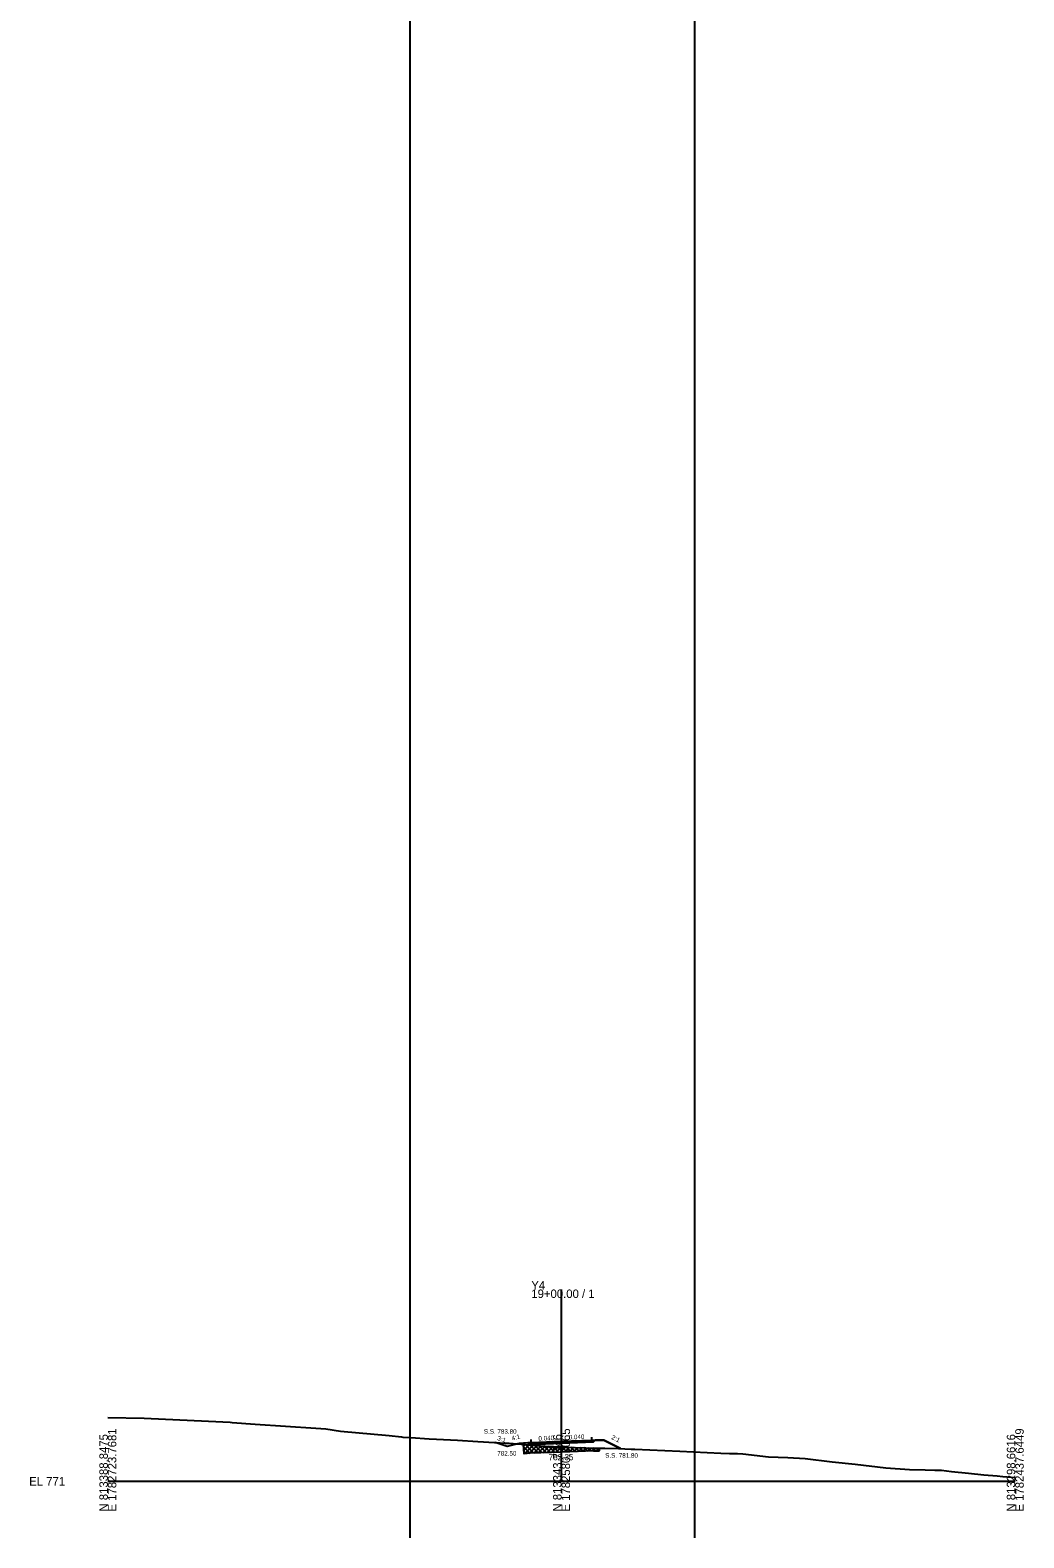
# Model space of a CAD drawing. Extents: x -26 to 3903, y -10 to 9562.
# Drawn here: x 974.3 to 1302.8, y 981.3 to 1479.6 of the extents above; entities that cross this region are included whole.
import ezdxf

# ---------------------------------------------------------------- set-up
doc = ezdxf.new("R2010")
doc.units = 0
for name, color, linetype in [('Exist Cross Section Cell', 7, 'Continuous'), ('Exist XS Center Line Elevation Label', 7, 'Continuous'), ('Exist XS Ground Line', 7, 'Continuous'), ('Prop XS Ditch Slope Text', 7, 'Continuous'), ('Prop XS Ditch Standard Text', 7, 'Continuous'), ('Prop XS Dump Level', 7, 'Continuous'), ('Prop XS Earthwork Shape', 7, 'Continuous'), ('Prop XS Earthwork Undercut', 7, 'Continuous'), ('Prop XS EOT Tick Mark', 7, 'Continuous'), ('Prop XS Finish Grade', 7, 'Continuous'), ('Prop XS Finish Grade Earthwork', 7, 'Continuous'), ('Prop XS Finish Grade Pavement', 7, 'Continuous'), ('Prop XS Pvmt Edge Slope', 7, 'Continuous'), ('Prop XS SE Text', 7, 'Continuous'), ('Prop XS Side Slope Text', 7, 'Continuous'), ('Prop XS SS Elevation Text', 7, 'Continuous'), ('Prop XS Subgrade Earthwork', 7, 'Continuous'), ('Prop XS Undercut Exc Hatch', 7, 'Continuous'), ('Scratch_Level_1', 7, 'Continuous'), ('Scratch_Level_2', 7, 'Continuous'), ('Scratch_Level_4', 7, 'Continuous'), ('Scratch_Level_6', 7, 'Continuous')]:
    doc.layers.add(name, color=color, linetype=linetype)

msp = doc.modelspace()

# ---------------------------------------------------------------- linework, layer by layer
at = {"layer": 'Exist Cross Section Cell'}
for p, q in [((1150, 1000), (1150, 1063.39)), ((1000, 1000), (1150, 1000)), ((1150, 1000), (1300, 1000))]:
    msp.add_line(p, q, dxfattribs=at)
at = {"layer": 'Exist XS Ground Line'}
for p, q in [((1000, 1021.13), (1011.96, 1020.92)), ((1011.96, 1020.92), (1037.96, 1019.6)), ((1037.96, 1019.6), (1040.4, 1019.5)), ((1040.4, 1019.5), (1041.07, 1019.45)), ((1041.07, 1019.45), (1048.74, 1018.93)), ((1048.74, 1018.93), (1068.81, 1017.56)), ((1068.81, 1017.56), (1072.02, 1017.39)), ((1072.02, 1017.39), (1076.91, 1016.62)), ((1076.91, 1016.62), (1092.96, 1015.09)), ((1092.96, 1015.09), (1097.12, 1014.66)), ((1097.12, 1014.66), (1097.51, 1014.61)), ((1097.51, 1014.61), (1100.13, 1014.46)), ((1100.13, 1014.46), (1106.24, 1014.08)), ((1106.24, 1014.08), (1108.69, 1013.95)), ((1108.69, 1013.95), (1115.61, 1013.56)), ((1115.61, 1013.56), (1122.3, 1013.15)), ((1122.3, 1013.15), (1127.87, 1012.81)), ((1127.87, 1012.81), (1131.34, 1012.64)), ((1131.34, 1012.64), (1132.64, 1012.58)), ((1132.64, 1012.58), (1138.01, 1012.14)), ((1138.01, 1012.14), (1141.64, 1011.84)), ((1141.64, 1011.84), (1144.56, 1011.64)), ((1144.56, 1011.64), (1150, 1011.35)), ((1150, 1011.35), (1150.63, 1011.32)), ((1150.63, 1011.32), (1158.01, 1011.11)), ((1158.01, 1011.11), (1162.5, 1010.97)), ((1162.5, 1010.97), (1164.35, 1010.99)), ((1164.35, 1010.99), (1168.84, 1010.83)), ((1168.84, 1010.83), (1172.96, 1010.67)), ((1172.96, 1010.67), (1174.18, 1010.59)), ((1174.18, 1010.59), (1189.07, 1009.95)), ((1189.07, 1009.95), (1202.68, 1009.27)), ((1202.68, 1009.27), (1205.5, 1009.22)), ((1205.5, 1009.22), (1208.16, 1009.19)), ((1208.16, 1009.19), (1209.9, 1009.08)), ((1209.9, 1009.08), (1218.39, 1008.08)), ((1218.39, 1008.08), (1224.8, 1007.88)), ((1224.8, 1007.88), (1230.59, 1007.57)), ((1230.59, 1007.57), (1239.46, 1006.47)), ((1239.46, 1006.47), (1247.1, 1005.69)), ((1247.1, 1005.69), (1257.22, 1004.44)), ((1257.22, 1004.44), (1265.08, 1003.89)), ((1265.08, 1003.89), (1270.24, 1003.74)), ((1270.24, 1003.74), (1273.4, 1003.68)), ((1273.4, 1003.68), (1275.59, 1003.64)), ((1275.59, 1003.64), (1278.88, 1003.26)), ((1278.88, 1003.26), (1284.53, 1002.69)), ((1284.53, 1002.69), (1289.66, 1002.18)), ((1289.66, 1002.18), (1294.02, 1001.8)), ((1294.02, 1001.8), (1295.89, 1001.55)), ((1295.89, 1001.55), (1300, 1001.22))]:
    msp.add_line(p, q, dxfattribs=at)
at = {"layer": 'Prop XS Dump Level'}
for p, q in [((1140, 1012.82), (1150, 1013.22)), ((1150, 1013.22), (1160, 1013.62))]:
    msp.add_line(p, q, dxfattribs=at)
at = {"layer": 'Prop XS Earthwork Shape'}
for points in [[(1135.41, 1012.35), (1132, 1011.5), (1128.09, 1012.8), (1131.34, 1012.64), (1132.64, 1012.58)], [(1138.87, 1012.73), (1136, 1012.5), (1135.41, 1012.35), (1138.01, 1012.14), (1141.64, 1011.84), (1144.56, 1011.64), (1150, 1011.35), (1150.63, 1011.32), (1158.01, 1011.11), (1162.5, 1010.97), (1164.35, 1010.99), (1168.84, 1010.83), (1169.47, 1010.8), (1164, 1013.54), (1161.1, 1013.6), (1160.56, 1013.06), (1150.02, 1012.64), (1139.39, 1012.21)]]:
    msp.add_lwpolyline(points, close=True, dxfattribs=at)
at = {"layer": 'Prop XS Earthwork Undercut'}
for p, q in [((1137.44, 1012.19), (1137.63, 1009.13)), ((1139.59, 1009.26), (1137.63, 1009.13)), ((1150.12, 1009.68), (1139.59, 1009.26)), ((1160.52, 1010.1), (1150.12, 1009.68)), ((1160.52, 1010.1), (1162.4, 1010.02)), ((1162.44, 1010.97), (1162.4, 1010.02))]:
    msp.add_line(p, q, dxfattribs=at)
at = {"layer": 'Prop XS EOT Tick Mark'}
for p, q in [((1140, 1012.82), (1140, 1013.82)), ((1160, 1013.62), (1160, 1014.62))]:
    msp.add_line(p, q, dxfattribs=at)
at = {"layer": 'Prop XS Finish Grade'}
for p, q in [((1140, 1012.82), (1138.87, 1012.73)), ((1160, 1013.62), (1161.1, 1013.6))]:
    msp.add_line(p, q, dxfattribs=at)
at = {"layer": 'Prop XS Finish Grade Earthwork'}
for p, q in [((1132, 1011.5), (1128.09, 1012.8)), ((1136, 1012.5), (1132, 1011.5)), ((1138.87, 1012.73), (1136, 1012.5)), ((1161.1, 1013.6), (1164, 1013.54)), ((1164, 1013.54), (1169.47, 1010.8))]:
    msp.add_line(p, q, dxfattribs=at)
at = {"layer": 'Prop XS Finish Grade Pavement'}
for p, q in [((1140, 1012.82), (1150, 1013.22)), ((1150, 1013.22), (1160, 1013.62))]:
    msp.add_line(p, q, dxfattribs=at)
at = {"layer": 'Prop XS Pvmt Edge Slope'}
for p, q in [((1140, 1012.82), (1139.39, 1012.21)), ((1160, 1013.62), (1160.56, 1013.06))]:
    msp.add_line(p, q, dxfattribs=at)
at = {"layer": 'Prop XS Subgrade Earthwork'}
for p, q in [((1139.39, 1012.21), (1138.87, 1012.73)), ((1139.39, 1012.21), (1150.02, 1012.64)), ((1150.02, 1012.64), (1160.56, 1013.06)), ((1160.56, 1013.06), (1161.1, 1013.6))]:
    msp.add_line(p, q, dxfattribs=at)
at = {"layer": 'Prop XS Undercut Exc Hatch'}
for p, q in [((1137.47, 1011.62), (1137.99, 1012.14)), ((1137.56, 1010.29), (1139.3, 1012.03)), ((1140, 1010.19), (1138.05, 1012.14)), ((1140, 1011.6), (1139.59, 1012.01)), ((1140, 1011.32), (1140.61, 1011.93)), ((1140, 1009.9), (1141.92, 1011.82)), ((1142.24, 1009.36), (1140, 1011.6)), ((1140.82, 1009.31), (1143.24, 1011.73)), ((1143.6, 1009.42), (1141.13, 1011.88)), ((1142.29, 1009.37), (1144.56, 1011.64)), ((1144.96, 1009.47), (1142.66, 1011.77)), ((1143.76, 1009.43), (1145.91, 1011.57)), ((1146.32, 1009.53), (1144.18, 1011.67)), ((1147.68, 1009.58), (1145.68, 1011.58)), ((1139.52, 1009.25), (1137.49, 1011.28)), ((1138.19, 1009.17), (1137.59, 1009.76)), ((1137.83, 1009.14), (1140, 1011.32)), ((1139.34, 1009.24), (1140, 1009.9)), ((1140.88, 1009.31), (1140, 1010.19)), ((1145.24, 1009.48), (1147.25, 1011.5)), ((1146.71, 1009.54), (1148.6, 1011.43)), ((1149.04, 1009.64), (1147.17, 1011.5)), ((1148.18, 1009.6), (1149.94, 1011.36)), ((1150, 1010.09), (1148.66, 1011.42)), ((1149.66, 1009.66), (1150, 1010)), ((1150, 1010), (1151.3, 1011.3)), ((1150.4, 1009.69), (1150, 1010.09)), ((1151.76, 1009.74), (1150.15, 1011.35)), ((1151.13, 1009.72), (1152.67, 1011.26)), ((1153.12, 1009.8), (1151.62, 1011.29)), ((1152.6, 1009.78), (1154.05, 1011.23)), ((1154.48, 1009.85), (1153.08, 1011.25)), ((1154.08, 1009.84), (1155.43, 1011.19)), ((1155.83, 1009.91), (1154.53, 1011.21)), ((1155.55, 1009.9), (1156.8, 1011.15)), ((1157.19, 1009.96), (1155.99, 1011.17)), ((1157.02, 1009.96), (1158.18, 1011.11)), ((1158.55, 1010.02), (1157.44, 1011.13)), ((1158.5, 1010.01), (1159.55, 1011.06)), ((1159.91, 1010.07), (1158.9, 1011.09)), ((1159.97, 1010.07), (1160, 1010.1)), ((1160, 1010.1), (1160.91, 1011.02)), ((1161.34, 1010.06), (1160.36, 1011.04)), ((1161.37, 1010.06), (1162.28, 1010.97)), ((1162.41, 1010.4), (1161.83, 1010.99))]:
    msp.add_line(p, q, dxfattribs=at)
at = {"layer": 'Scratch_Level_1'}
msp.add_line((1100, 981.31), (1100, 2030.41), dxfattribs=at)
at = {"layer": 'Scratch_Level_2'}
msp.add_line((1194.07, 981.31), (1194.07, 2030.41), dxfattribs=at)
at = {"layer": 'Scratch_Level_4'}
msp.add_lwpolyline([(1128.09, 1012.8), (1131.34, 1012.64), (1132.64, 1012.58), (1135.41, 1012.35), (1132, 1011.5)], close=True, dxfattribs=at)
at = {"layer": 'Scratch_Level_6'}
msp.add_lwpolyline([(1137.44, 1012.19), (1138.01, 1012.14), (1141.64, 1011.84), (1144.56, 1011.64), (1150, 1011.35), (1150.63, 1011.32), (1158.01, 1011.11), (1162.44, 1010.97), (1162.4, 1010.02), (1160.52, 1010.1), (1150.12, 1009.68), (1139.59, 1009.26), (1137.63, 1009.13)], close=True, dxfattribs=at)

# ---------------------------------------------------------------- texts
at = {"layer": 'Exist Cross Section Cell'}
for s, p in [('Y4', (1140, 1063.39)), ('19+00.00 / 1', (1140, 1060.59)), ('EL 771', (974, 998.6))]:
    msp.add_text(s, height=2.8, dxfattribs=at).set_placement(p)
for s, p in [('E 1782723.7681', (1002.8, 990)), ('E 1782580.7065', (1152.8, 990)), ('E 1782437.6449', (1302.8, 990)), ('N 813388.8475', (1000, 990)), ('N 813343.7546', (1150, 990)), ('N 813298.6616', (1300, 990))]:
    msp.add_text(s, height=2.8, rotation=90, dxfattribs=at).set_placement(p)
at = {"layer": 'Exist XS Center Line Elevation Label'}
msp.add_text('782.35', height=2, dxfattribs=at).set_placement((1145.74, 1006.97))
at = {"layer": 'Prop XS Ditch Slope Text'}
msp.add_text('4:1', height=1.5, rotation=14.0362, dxfattribs=at).set_placement((1133.64, 1013.45))
at = {"layer": 'Prop XS Ditch Standard Text'}
msp.add_text('782.50', height=1.5, dxfattribs=at).set_placement((1128.74, 1008.5))
at = {"layer": 'Prop XS Dump Level'}
for p in [(1136, 1012.46), (1164, 1013.5)]:
    msp.add_text('Case1', height=0.04, dxfattribs=at).set_placement(p)
at = {"layer": 'Prop XS SE Text'}
for p in [(1142.38, 1013.41), (1152.38, 1013.81)]:
    msp.add_text('0.040', height=1.5, rotation=2.2906, dxfattribs=at).set_placement(p)
at = {"layer": 'Prop XS Side Slope Text'}
for s, rotation, p in [('3:1', 342.2871, (1128.63, 1013.66)), ('2:1', 333.4349, (1166.32, 1014.06))]:
    msp.add_text(s, height=1.5, rotation=rotation, dxfattribs=at).set_placement(p)
at = {"layer": 'Prop XS SS Elevation Text'}
for s, p in [('S.S. 783.80', (1124.31, 1015.73)), ('S.S. 781.80', (1164.42, 1007.8))]:
    msp.add_text(s, height=1.5, dxfattribs=at).set_placement(p)

doc.saveas('drawing.dxf')
